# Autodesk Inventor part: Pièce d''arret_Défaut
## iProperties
Shininess: 64.0
Length Units: 11269
Angle Units: 11279
Time Units: 11290
Mass Units: 11283
Length Display Precision: 3
Angle Display Precision: 2
Compacted: True
Part Number: Pièce d''arret_Défaut
Document SubType Name: Modeling
Created: 2006-11
Material: Par défaut
Designer: profs_sti
Density: 0.0
Volumn: 0.0
Area: 0.0
PropertySet Name: Model Information
Control State: 0
Master: False
Checked Out: False
Author: profs_sti
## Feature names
1. Base1
